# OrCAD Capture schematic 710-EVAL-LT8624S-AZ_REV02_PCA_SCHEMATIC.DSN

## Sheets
1 LT8624S: size B; note: 18V, 4A MONOLITHIC SYNCHRONOUS STEP-DOWN
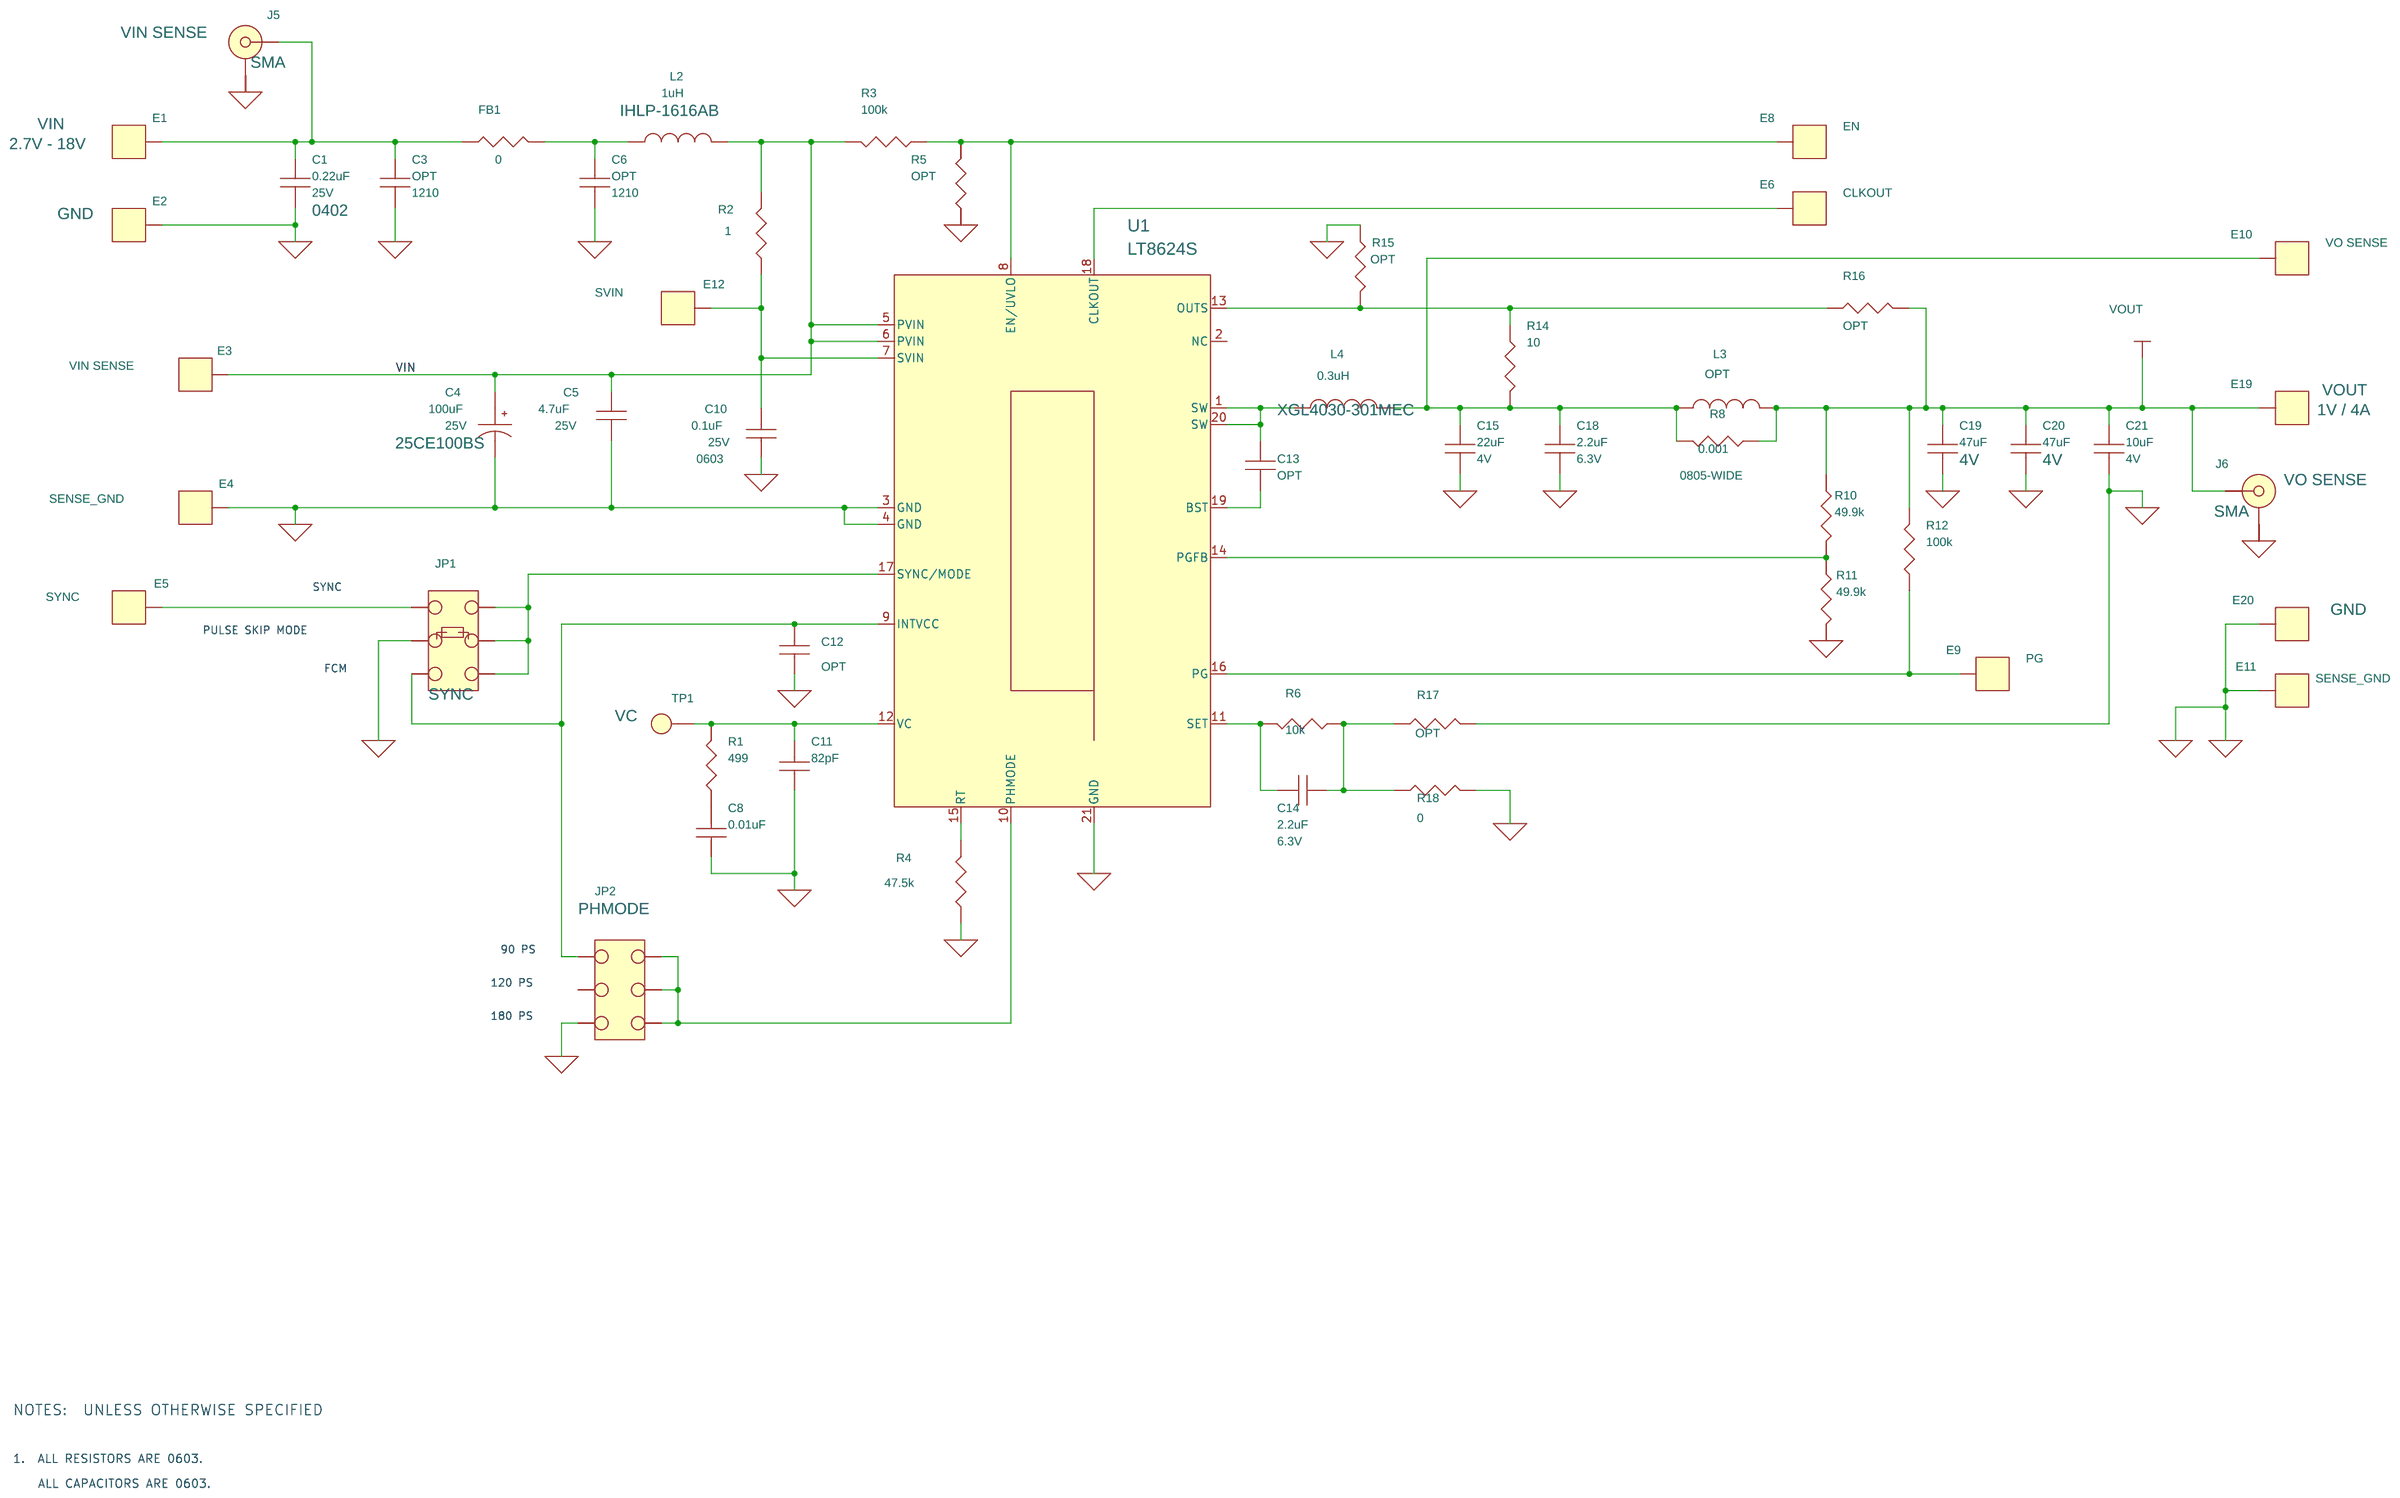
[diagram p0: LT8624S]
2 HARDWARE
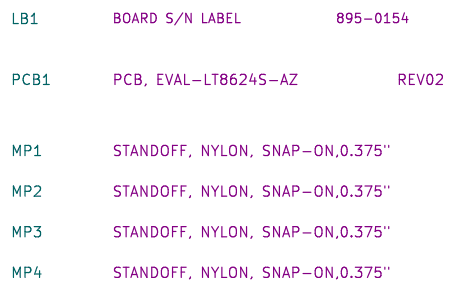
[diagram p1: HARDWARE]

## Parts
sheet HARDWARE
LB1  LABEL  [895-0154_REV01]
MP1  STANDOFF, NYLON, SNAP-ON  [KEYSTONE_8829-8834]
MP2  STANDOFF, NYLON, SNAP-ON  [KEYSTONE_8829-8834]
MP3  STANDOFF, NYLON, SNAP-ON  [KEYSTONE_8829-8834]
MP4  STANDOFF, NYLON, SNAP-ON  [KEYSTONE_8829-8834]
PCB1  PCB, EVAL-LT8624S-AZ
sheet LT8624S
C1  0.22uF  [CC0402N]
C3  OPT  [CC1210N]
C4  100uF  [SUNCON_CE-BS_6.3X7.7]
C5  4.7uF  [CC0603N]
C6  OPT  [CC1210N]
C8  0.01uF  [CC0603N]
C10  0.1uF  [CC0603N]
C11  82pF  [CC0603N]
C12  OPT  [CC0603N]
C13  OPT  [CC0603N]
C14  2.2uF  [CC0603N]
C15  22uF  [CC0603N]
C18  2.2uF  [CC0603N]
C19  47uF  [CC0603N]
C20  47uF  [CC0603N]
C21  10uF  [CC0603N]
E1  TEST POINT  [KEYSTONE_5019]
E2  TEST POINT  [KEYSTONE_5019]
E3  TEST POINT  [TE-1625854-2]
E4  TEST POINT  [TE-1625854-2]
E5  TEST POINT  [TE-1625854-2]
E6  TEST POINT  [TE-1625854-2]
E8  TEST POINT  [TE-1625854-2]
E9  TEST POINT  [TE-1625854-2]
E10  TEST POINT  [TE-1625854-2]
E11  TEST POINT  [TE-1625854-2]
E12  TEST POINT  [TE-1625854-2]
E19  TEST POINT  [KEYSTONE_5019]
E20  TEST POINT  [KEYSTONE_5019]
FB1  0  [CR0603N]
J5  RF/COAX,SMA JACK  [MOLEX-732511350]
J6  RF/COAX,SMA JACK  [MOLEX-732511350]
JP1  HDR  [HD2X3-079]
JP2  HDR  [HD2X3-079]
L2  1uH  [VISHAY-IHLP-1616AB-01]
L3  OPT  [COILCRAFT-XEL4030]
L4  0.3uH  [COILCRAFT-XGL4030]
R1  499  [CR0603N]
R2  1  [CR0603N]
R3  100k  [CR0603N]
R4  47.5k  [CR0603N]
R5  OPT  [CR0603N]
R6  10k  [CR0603N]
R8  0.001  [SUSUMU-KRL2012]
R10  49.9k  [CR0603N]
R11  49.9k  [CR0603N]
R12  100k  [CR0603N]
R14  10  [CR0603N]
R15  OPT  [CR0603N]
R16  OPT  [CR0603N]
R17  OPT  [CR0603N]
R18  0  [CR0603N]
TP1  TEST PAD  [PADSTYLE1]
U1  LT8624S  [LTC-LQFN-20-1602]
XJP1  SHUNT
XJP2  SHUNT

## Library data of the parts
LB1 = BLANK_LABEL: LABEL SPEC, DEMO BOARD SERIAL NUMBER; Inventory Qty: 0; Manufacturer: BRADY; Manufacturer PN: THT-96-717-10; PART_FIELD_01: BOARD S/N LABEL; PART_NUMBER: 895-0154
MP1-MP4 = BLANK_PINLESS_MECHANICAL_PART: STANDOFF, NYLON, SNAP-ON,0.375"; CLASS: DISCRETE; FPLIST: KEYSTONE_8829-8834,KEYSTONE_8832; Inventory Qty: 202920; Manufacturer: KEYSTONE; Manufacturer PN: 8832; PART_NUMBER: 763-0008
PCB1 = BLANK_PCB_PART: BOM Notes: REV02; CLASS: DISCRETE; Inventory Qty: 0; Manufacturer: ADI APPROVED SUPPLIER; Manufacturer PN: 600-EVAL-LT8624S-AZ; PART_NUMBER: 600-EVAL-LT8624S-AZ
C1 = CAP: CAP.,0.22uF,X7R,25V,10%,0402,AEC-Q200; CLASS: DISCRETE; Dielectric Type: X7R; FPLIST: CC0402N,CC0402L,CC0402M; Inventory Qty: 0; Manufacturer: TDK; Manufacturer PN: CGA2B3X7R1E224K050BB; PART_NUMBER: 150-1895; Package Size: 0402; Rated Voltage: 25V; Tolerance: 10%
C3 C6 = CAP: CAP., OPTION, 1210; CLASS: DISCRETE; FPLIST: CC1210N,CC1210L,CC1210M; PART_NUMBER: 150-3035; Package Size: 1210; Package Type: SMD
C4 = CAP_P_ALT: CAP.,100uF,ALUM ELECT,25V,20%,6.3x7.7mm,CE-BS Series; CLASS: DISCRETE; Dielectric Type: ALUM ELECT; Inventory Qty: 0; Manufacturer: SUN ELECTRONIC INDUSTRIES CORP; Manufacturer PN: 25CE100BS; PART_NUMBER: 150-1793; Package Size: 6.3x7.7mm; Rated Voltage: 25V; Tolerance: 20%
C5 = CAP: CAP.,4.7uF,X5R,25V,10%,0603; CLASS: DISCRETE; Dielectric Type: X5R; FPLIST: CC0603N,CC0603L,CC0603M; Inventory Qty: 10846; Manufacturer: MURATA; Manufacturer PN: GRM188R61E475KE15D; PART_NUMBER: 150-0445; Package Size: 0603; Rated Voltage: 25V; Tolerance: 10%
C8 = CAP: CAP.,0.01uF,X7R,50V,10%,0603; CLASS: DISCRETE; Dielectric Type: X7R; FPLIST: CC0603N,CC0603L,CC0603M; Inventory Qty: 28283; Manufacturer: AVX; Manufacturer PN: 06035C103KAT2A; PART_NUMBER: 150-0002; Package Size: 0603; Rated Voltage: 50V; Tolerance: 10%
C10 = CAP: CAP.,0.1uF,X7R,25V,10%,0603; CLASS: DISCRETE; Dielectric Type: X7R; FPLIST: CC0603N,CC0603L,CC0603M; Inventory Qty: 60590; Manufacturer: AVX; Manufacturer PN: 06033C104KAT2A; PART_NUMBER: 150-0065; Package Size: 0603; Rated Voltage: 25V; Tolerance: 10%
C11 = CAP: CAP.,82pF,X7R,50V,10%,0603; CLASS: DISCRETE; Dielectric Type: X7R; FPLIST: CC0603N,CC0603L,CC0603M; Inventory Qty: 0; Manufacturer: KEMET; Manufacturer PN: C0603C820K5RAC7867; PART_NUMBER: 150-1854; Package Size: 0603; Rated Voltage: 50V; Tolerance: 10%
C12 C13 = CAP: CAP., OPTION, 0603; CLASS: DISCRETE; FPLIST: CC0603N,CC0603L,CC0603M; PART_NUMBER: 150-3038; Package Size: 0603; Package Type: SMD
C14 C18 = CAP: CAP.,2.2uF,X7R,6.3V,10%,0603,AEC-Q200; CLASS: DISCRETE; Dielectric Type: X7R; FPLIST: CC0603N,CC0603L,CC0603M; Inventory Qty: 0; Manufacturer: MURATA; Manufacturer PN: GCM188R70J225KE22J; PART_NUMBER: 150-1897; Package Size: 0603; Rated Voltage: 6.3V; Temperature Coefficient: X7R; Tolerance: 10%
C15 = CAP: CAP.,22uF,X5R,4V,20%,0603,NO SUBS. ALLOWED; CLASS: DISCRETE; Dielectric Type: X5R; FPLIST: CC0603N,CC0603L,CC0603M; Inventory Qty: 4000; Manufacturer: MURATA; Manufacturer PN: GRM188R60G226MEA0D; PART_NUMBER: 150-2561; Package Size: 0603; Package Type: Surface Mount, MLCC; Rated Voltage: 4V; Temperature Coefficient: X5R; Tolerance: 20%
C19 C20 = CAP: CAP.,47uF,X5R,4V,20%,0603; CLASS: DISCRETE; Dielectric Type: X5R; FPLIST: CC0603N,CC0603L,CC0603M; Inventory Qty: 0; Manufacturer: MURATA; Manufacturer PN: GRM188R60G476ME15D; PART_NUMBER: 150-1834; Package Size: 0603; Package Type: Surface Mount, MLCC; Rated Voltage: 4V; Temperature Coefficient: X5R; Tolerance: 20%
C21 = CAP: CAP.,10uF,X7S,4V,20%,0603; CLASS: DISCRETE; Dielectric Type: X7S; FPLIST: CC0603N,CC0603L,CC0603M; Inventory Qty: 4000; Manufacturer: TDK; Manufacturer PN: C1608X7S0G106M080AB; PART_NUMBER: 150-1816; Package Size: 0603; Rated Voltage: 4V; Temperature Coefficient: X7S; Tolerance: 20%
E1 = MP-PINNED: TEST POINT,SILVER PLATE,PHOSPHOR BRONZE,3.81x2.03mm,2.29mm H,SMT; 10th Part Field: 2.7V - 18V; 9th Part Field: VIN; CLASS: DISCRETE; Inventory Qty: 40128; Manufacturer: KEYSTONE; Manufacturer PN: 5019; PART_NUMBER: 260-0018; Package Size: 0.15" L x 0.080" W
E2 E20 = MP-PINNED: TEST POINT,SILVER PLATE,PHOSPHOR BRONZE,3.81x2.03mm,2.29mm H,SMT; 10th Part Field: GND; 9th Part Field: GND; CLASS: DISCRETE; Inventory Qty: 40128; Manufacturer: KEYSTONE; Manufacturer PN: 5019; PART_NUMBER: 260-0018; Package Size: 0.15" L x 0.080" W
E3 = MP-PINNED: TEST POINT,0805,2x1.25x1.45mm,PROBE PAD,FOIL,VERT,SMT,NATURAL; 10th Part Field: VIN SENSE; CLASS: DISCRETE; Inventory Qty: 0; Manufacturer: TE CONNECTIVITY; Manufacturer PN: 1625854-2; PART_NUMBER: 260-2662
E4 = MP-PINNED: TEST POINT,0805,2x1.25x1.45mm,PROBE PAD,FOIL,VERT,SMT,NATURAL; 10th Part Field: SENSE_GND; 9th Part Field: 1.5V - 18V; CLASS: DISCRETE; Inventory Qty: 0; Manufacturer: TE CONNECTIVITY; Manufacturer PN: 1625854-2; PART_NUMBER: 260-2662
E5 = MP-PINNED: TEST POINT,0805,2x1.25x1.45mm,PROBE PAD,FOIL,VERT,SMT,NATURAL; 10th Part Field: SYNC; 9th Part Field: 1.5V - 18V; CLASS: DISCRETE; Inventory Qty: 0; Manufacturer: TE CONNECTIVITY; Manufacturer PN: 1625854-2; PART_NUMBER: 260-2662
E6 = MP-PINNED: TEST POINT,0805,2x1.25x1.45mm,PROBE PAD,FOIL,VERT,SMT,NATURAL; 10th Part Field: CLKOUT; CLASS: DISCRETE; Inventory Qty: 0; Manufacturer: TE CONNECTIVITY; Manufacturer PN: 1625854-2; PART_NUMBER: 260-2662
E8 = MP-PINNED: TEST POINT,0805,2x1.25x1.45mm,PROBE PAD,FOIL,VERT,SMT,NATURAL; 10th Part Field: EN; CLASS: DISCRETE; Inventory Qty: 0; Manufacturer: TE CONNECTIVITY; Manufacturer PN: 1625854-2; PART_NUMBER: 260-2662
E9 = MP-PINNED: TEST POINT,0805,2x1.25x1.45mm,PROBE PAD,FOIL,VERT,SMT,NATURAL; 10th Part Field: PG; CLASS: DISCRETE; Inventory Qty: 0; Manufacturer: TE CONNECTIVITY; Manufacturer PN: 1625854-2; PART_NUMBER: 260-2662
E10 = MP-PINNED: TEST POINT,0805,2x1.25x1.45mm,PROBE PAD,FOIL,VERT,SMT,NATURAL; 10th Part Field: VO SENSE; CLASS: DISCRETE; Inventory Qty: 0; Manufacturer: TE CONNECTIVITY; Manufacturer PN: 1625854-2; PART_NUMBER: 260-2662
E11 = MP-PINNED: TEST POINT,0805,2x1.25x1.45mm,PROBE PAD,FOIL,VERT,SMT,NATURAL; 10th Part Field: SENSE_GND; CLASS: DISCRETE; Inventory Qty: 0; Manufacturer: TE CONNECTIVITY; Manufacturer PN: 1625854-2; PART_NUMBER: 260-2662
E12 = MP-PINNED: TEST POINT,0805,2x1.25x1.45mm,PROBE PAD,FOIL,VERT,SMT,NATURAL; 10th Part Field: SVIN; CLASS: DISCRETE; Inventory Qty: 0; Manufacturer: TE CONNECTIVITY; Manufacturer PN: 1625854-2; PART_NUMBER: 260-2662
E19 = MP-PINNED: TEST POINT,SILVER PLATE,PHOSPHOR BRONZE,3.81x2.03mm,2.29mm H,SMT; 10th Part Field: 1V / 4A; 9th Part Field: VOUT; CLASS: DISCRETE; Inventory Qty: 40128; Manufacturer: KEYSTONE; Manufacturer PN: 5019; PART_NUMBER: 260-0018; Package Size: 0.15" L x 0.080" W
FB1 R18 = RES: RES.,0 OHM,1/10W,0603,AEC-Q200; CLASS: DISCRETE; FPLIST: CR0603N,CR0603L,CR0603M; Inventory Qty: 676258; Manufacturer: VISHAY; Manufacturer PN: CRCW06030000Z0EA; PART_NUMBER: 100-0009; Package Size: 0603; Rated Power: 1/10W
J5 = COAX_CONN_5PIN_ALT1: CONN.,RF/COAX,SMA JACK,FEMALE,1PORT,VERT,ST,SMT,50 OHMS,Au; 10th Part Field: VIN SENSE; 9th Part Field: SMA; CLASS: IO; Inventory Qty: 2280; Manufacturer: MOLEX; Manufacturer PN: 0732511350; PART_NUMBER: 250-0959
J6 = COAX_CONN_5PIN_ALT1: CONN.,RF/COAX,SMA JACK,FEMALE,1PORT,VERT,ST,SMT,50 OHMS,Au; 10th Part Field: VO SENSE; 9th Part Field: SMA; CLASS: IO; Inventory Qty: 2280; Manufacturer: MOLEX; Manufacturer PN: 0732511350; PART_NUMBER: 250-0959
JP1 = HEADER_2X3_.079: CONN.,HDR,MALE,2x3,2mm,VERT,ST,THT; 9th Part Field: SYNC; CLASS: IO; FPLIST: HD2X3-079,WURTH-62000621121; Inventory Qty: 17651; Manufacturer: WURTH ELEKTRONIK; Manufacturer PN: 62000621121; PART_NUMBER: 250-0483
JP2 = HEADER_2X3_.079: CONN.,HDR,MALE,2x3,2mm,VERT,ST,THT; 9th Part Field: PHMODE; CLASS: IO; FPLIST: HD2X3-079,WURTH-62000621121; Inventory Qty: 17651; Manufacturer: WURTH ELEKTRONIK; Manufacturer PN: 62000621121; PART_NUMBER: 250-0483
L2 = IND_ALT: IND.,1uH,PWR,SHIELDED,20%,4A,52.5mOHMS,1616AB,IHLP-01 Series; 9th Part Field: IHLP-1616AB; CLASS: DISCRETE; Inventory Qty: 4500; Manufacturer: VISHAY; Manufacturer PN: IHLP1616ABER1R0M01; PART_NUMBER: 200-0760; Package Size: 1616AB; Tolerance: 20%
L3 = IND_ALT: IND., OPTION; CLASS: DISCRETE; Package Size: USER ASSIGNED
L4 = IND: IND.,0.3uH,PWR,20%,21.2A,3.4mOHMS,SMD,AEC-Q200,SHIELDED; CLASS: DISCRETE; Inventory Qty: 0; Manufacturer: COILCRAFT; Manufacturer PN: XGL4030-301MEC; PART_NUMBER: 200-0841; Package Size: SMD; Tolerance: 20%
R1 = RES: RES.,499 OHMS,1%,1/10W,0603,AEC-Q200; CLASS: DISCRETE; FPLIST: CR0603N,CR0603L,CR0603M; Inventory Qty: 19400; Manufacturer: VISHAY; Manufacturer PN: CRCW0603499RFKEA; PART_NUMBER: 100-2777; Package Size: 0603; Rated Power: 1/10W; Temperature Coefficient: 100ppm/C; Tolerance: 1%
R2 = RES: RES.,1 OHM,1%,1/10W,0603,AEC-Q200; CLASS: DISCRETE; FPLIST: CR0603N,CR0603L,CR0603M; Inventory Qty: 53360; Manufacturer: NIC; Manufacturer PN: NRC06F1R00TRF; PART_NUMBER: 100-0238; Package Size: 0603; Rated Power: 1/10W; Temperature Coefficient: 100ppm/C; Tolerance: 1%
R3 R12 = RES: RES.,100k OHMS,1%,1/10W,0603,AEC-Q200; CLASS: DISCRETE; FPLIST: CR0603N,CR0603L,CR0603M; Inventory Qty: 185604; Manufacturer: VISHAY; Manufacturer PN: CRCW0603100KFKEA; PART_NUMBER: 100-0343; Package Size: 0603; Rated Power: 1/10W; Temperature Coefficient: +/-100ppm; Tolerance: 1%
R4 = RES: RES.,47.5k OHMS,1%,1/10W,0603; CLASS: DISCRETE; FPLIST: CR0603N,CR0603L,CR0603M; Inventory Qty: 67863; Manufacturer: VISHAY; Manufacturer PN: CRCW060347K5FKEA; PART_NUMBER: 100-2554; Package Size: 0603; Rated Power: 1/10W; Temperature Coefficient: 100ppm/C; Tolerance: 1%
R5 R15-R17 = RES: RES., OPTION, 0603; CLASS: DISCRETE; FPLIST: CR0603N,CR0603L,CR0603M; PART_NUMBER: 100-2374; Package Size: 0603
R6 = RES: RES.,10k OHMS,1%,1/10W,0603,AEC-Q200; CLASS: DISCRETE; FPLIST: CR0603N,CR0603L,CR0603M; Inventory Qty: 194448; Manufacturer: VISHAY; Manufacturer PN: CRCW060310K0FKEA; PART_NUMBER: 100-2012; Package Size: 0603; Rated Power: 1/10W; Temperature Coefficient: +/-100ppm/C; Tolerance: 1%
R8 = RES: RES.,0.001 OHM,5%,1W,0805,LONG SIDE WRAP AROUND,METAL,SENSE,AEC-Q200; 9th Part Field: 0805-WIDE; CLASS: DISCRETE; FPLIST: SUSUMU-KRL2012,SUSUMU-KRL2012-3m,USER_ASSIGNED; Inventory Qty: 0; Manufacturer: SUSUMU; Manufacturer PN: KRL2012E-M-R001-J-T5; PART_NUMBER: 100-1904; Package Size: 0805,LONG SIDE WRAP AROUND; Rated Power: 1W; Temperature Coefficient: +/-150ppm; Tolerance: 5%
R10 R11 = RES: RES.,49.9k OHMS,1%,1/10W,0603; CLASS: DISCRETE; FPLIST: CR0603N,CR0603L,CR0603M; Inventory Qty: 100527; Manufacturer: NIC; Manufacturer PN: NRC06F4992TRF; PART_NUMBER: 100-0303; Package Size: 0603; Rated Power: 1/10W; Temperature Coefficient: 100ppm/C; Tolerance: 1%
R14 = RES: RES.,10 OHMS,1%,1/10W,0603; CLASS: DISCRETE; FPLIST: CR0603N,CR0603L,CR0603M; Inventory Qty: 152750; Manufacturer: VISHAY; Manufacturer PN: CRCW060310R0FKEA; PART_NUMBER: 100-2306; Package Size: 0603; Rated Power: 1/10W; Temperature Coefficient: 100ppm/C; Tolerance: 1%
TP1 = PAD_STYLE_C: TESTPOINT, PCB COPPER FEATURE; 10th Part Field: VC; CLASS: IO; FPLIST: PADSTYLE1,PADSTYLE2,PADSTYLE3,PADSTYLE4,PADSTYLE5,PADSTYLE6,PADSTYLE7,PADSTYLE8; Manufacturer: N/A; Manufacturer PN: N/A
U1 = LT8624S-LQFN: IC,SYN STEP-DOWN SILENT SWITCHER,LQFN-20,PRELIM.; CLASS: IC; Inventory Qty: 0; Manufacturer: ANALOG DEVICES; Manufacturer PN: LT8624SAV#PBF; PART_NUMBER: LT8624SAV#PBF; Package Type: LQFN-20
XJP1 XJP2 = SHUNT_2MM_C: CONN.,SHUNT,FEMALE,2-POS,2mm; CLASS: IO; Inventory Qty: 64675; Manufacturer: Wurth Elektronik; Manufacturer PN: 60800213421; PART_NUMBER: 250-0485

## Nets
GND: C1.2 C3.2 C4.2 C5.2 C6.2 C8.1 C10.1 C11.1 C12.1 C15.2 C18.2 C19.2 C20.2 C21.2 E2.1 E4.1 E11.1 E20.1 J5.2 J5.3 J5.4 J5.5 J6.2 J6.3 J6.4 J6.5 JP1.3 JP2.5 R4.1 R5.2 R11.1 R15.1 R17.2 R18.2 U1.3(GND) U1.4(GND) U1.21(GND)
VIN: C4.1 C5.1 E3.1 L2.2 R2.1 R3.2 U1.5(PVIN) U1.6(PVIN)
VOUT: C19.1 C20.1 C21.1 E19.1 J6.1 L3.2 R8.1 R10.2 R12.1 R16.1
N17263236: C11.2 R1.2 TP1.1 U1.12(VC)
N17263477: JP1.2 JP1.4 JP1.6 U1.17(SYNC/MODE)
N17263500: E5.1 JP1.1
N17263509: C12.2 JP1.5 JP2.1 U1.9(INTVCC)
N17265521: C1.1 C3.1 E1.1 FB1.1 J5.1
N17265531: C6.1 FB1.2 L2.1
N17266354: E8.1 R3.1 R5.1 U1.8(EN/UVLO)
N17268060: R4.2 U1.15(RT)
N17268975: E9.1 R12.2 U1.16(PG)
N17271151: C15.1 C18.1 E10.1 L3.1 L4.2 R8.2 R14.2
N17271791: JP2.2 JP2.4 JP2.6 U1.10(PHMODE)
N17279966: C10.2 E12.1 R2.2 U1.7(SVIN)
N17284744: C14.2 R6.1 U1.11(SET)
N17284751: C14.1 R6.2 R17.1 R18.1
N17294738: C13.1 L4.1 U1.1(SW) U1.20(SW)
N17294971: E6.1 U1.18(CLKOUT)
N17327079: C13.2 U1.19(BST)
N17329450: R10.1 R11.2 U1.14(PGFB)
N17334325: R14.1 R15.2 R16.2 U1.13(OUTS)
N17464659: C8.2 R1.1

Not connected (* = marked no-connect by the designer): JP2 3; U1 2(NC)

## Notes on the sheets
sheet 1
- SYNC
- PULSE SKIP MODE
- FCM
- 90 PS
- 120 PS
- 180 PS
- NOTES:  UNLESS OTHERWISE SPECIFIED
- 1.  ALL RESISTORS ARE 0603.
- ALL CAPACITORS ARE 0603.
